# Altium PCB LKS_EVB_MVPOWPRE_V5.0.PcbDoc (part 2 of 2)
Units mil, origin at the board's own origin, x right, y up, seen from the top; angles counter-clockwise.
Board outline 11300 x 7874.02 mil, 2 copper layers (Top Layer, Bottom Layer); 150 components, 96 nets, 404 pads, 334 vias.
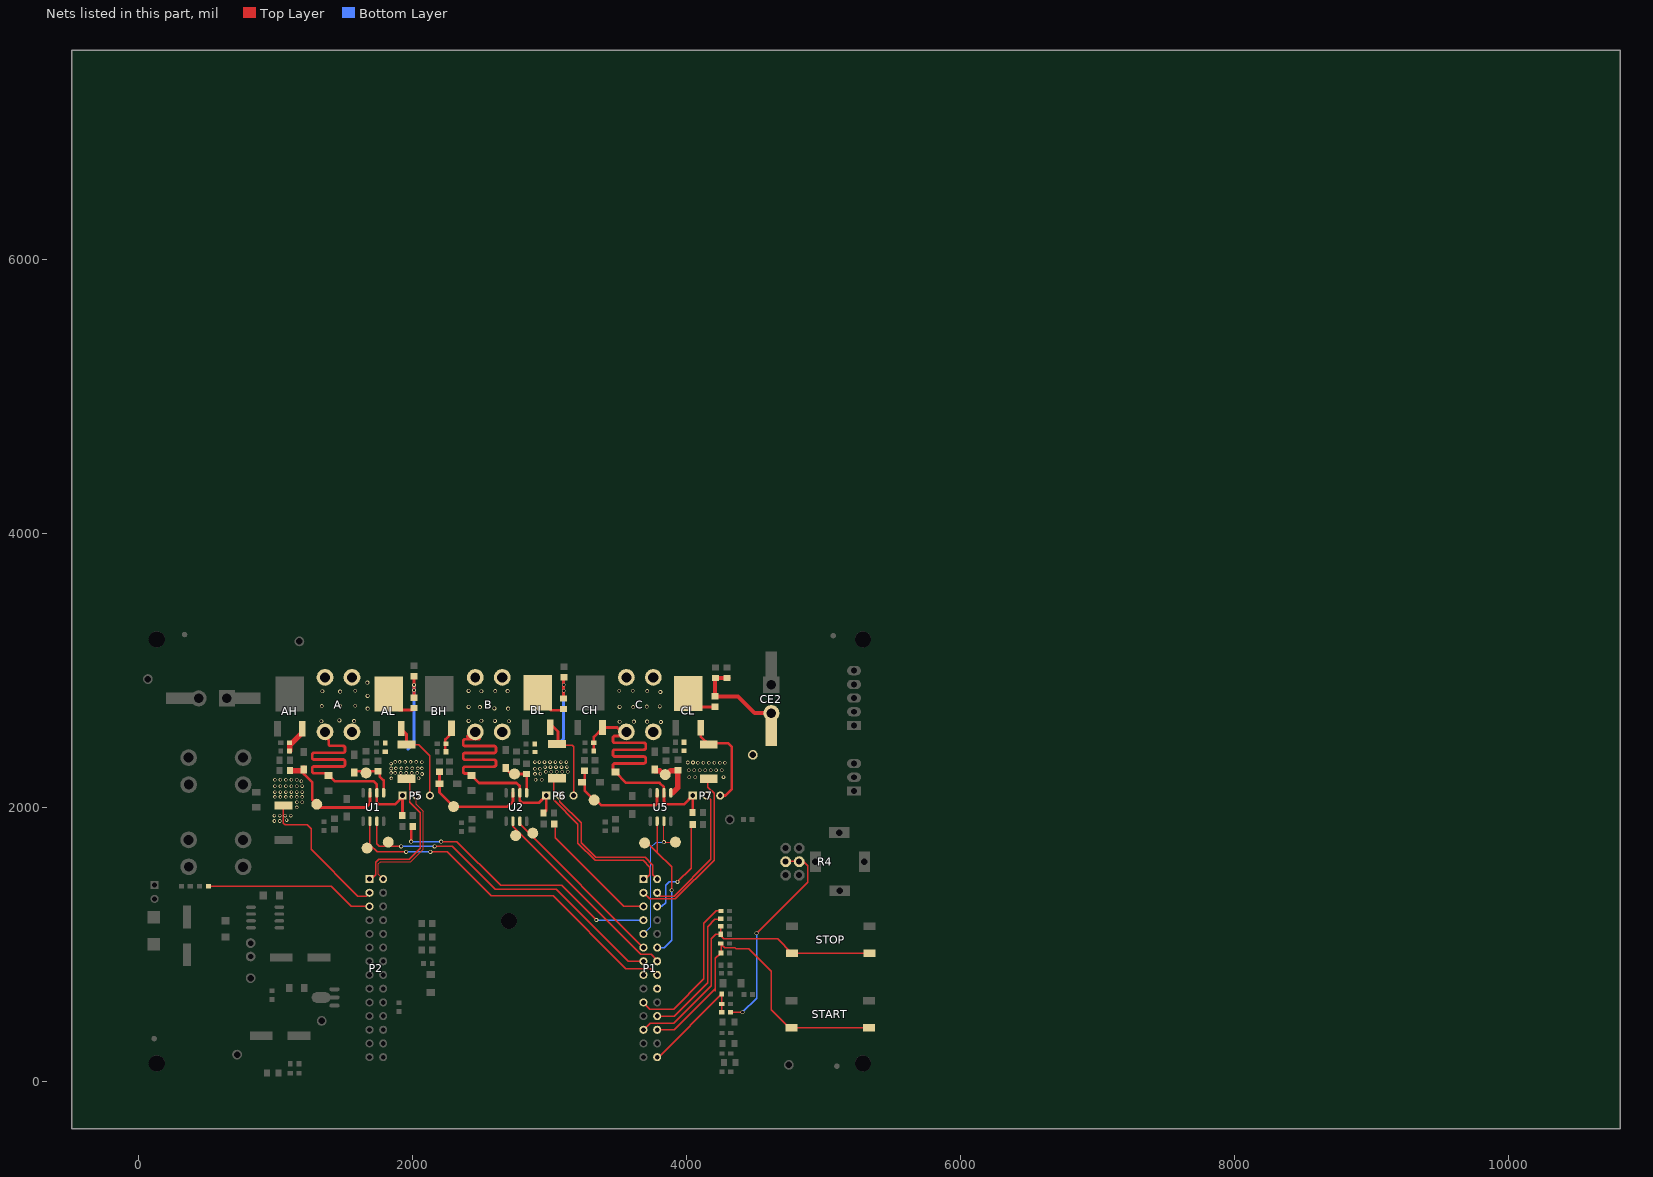
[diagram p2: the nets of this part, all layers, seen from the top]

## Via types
v1: diameter 26, hole 16, Top Layer to Bottom Layer, 130 vias
v2: diameter 28, hole 18, Top Layer to Bottom Layer, 77 vias
v3: diameter 26, hole 18, Top Layer to Bottom Layer, 55 vias
v4: diameter 28, hole 20, Top Layer to Bottom Layer, 54 vias
v5: diameter 23.62, hole 15.75, Top Layer to Bottom Layer, 14 vias
v6: diameter 27.99, hole 20, Top Layer to Bottom Layer, 4 vias

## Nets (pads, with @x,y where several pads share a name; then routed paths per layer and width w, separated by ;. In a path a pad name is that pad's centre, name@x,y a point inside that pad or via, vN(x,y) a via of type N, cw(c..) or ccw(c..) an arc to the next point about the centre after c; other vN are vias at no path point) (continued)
PGND: C25.1 C26.1 C27.1 CE2.2 G1.1 P1.1 P1.2 P2.1 P2.2 R15.2 R16.1 R17.2 R28.1 R29.1 R30.1 R49.2 R69.1 | length 6483
  Top Layer w10: R69.1@1054.64,2011.11 1054.64,1884.12 1067.42,1871.33 1228.67,1871.33 1256.18,1843.82 1256.18,1692.96 1598.21,1350.93 1661.68,1350.93 ; P2.1@1692.67,1471.01 1727.92,1506.26 1727.92,1597.92 1751.19,1621.19 1974.19,1621.19 2054.38,1701.38 2054.38,1959.09 1975.85,2037.61 R15.2@1975.85,2199.1 ; R16.1@3026.4,2195.53 3026.4,2052.72 3204.47,1874.66 3204.47,1735.48 3329.09,1610.86 3682.02,1610.86 3730.05,1562.83 3730.05,1508.37 3696.87,1475.19 P1.1@3682.62,1475.19 ; P1.2@3682.62,1375.19 3727.73,1330.08 3915.11,1330.08 4197.64,1612.61 4197.64,2100.51 4150.95,2147.2 4150.83,2147.2 R17.2@4150.83,2198.71
  Top Layer w20: R28.1@2007.36,2802.08 C25.1@2007.36,2941.01 ; R29.1@3099.13,2793.46 C26.1@3099.13,2931.12
  Top Layer w30: C27.1@4203.92,2942.41 4203.92,2808.13 4372.39,2808.13 4494.4,2686.11 CE2.2@4615.74,2686.11 ; C27.1@4204.13,2942.2 R49.2@4303.26,2942.2
  Bottom Layer w20: 1963.13,2423.19 2007.36,2467.42 v2@2007.36,2889.83 ; 3067.37,2467.7 3099.18,2499.51 v3(3099.18,2893.01)
  other v1: 988.91,1899.15 1027.94,1899.15 1077.76,1905.51 988.91,1938.79 1027.94,1938.79 1067.42,1938.79 1108.08,1938.79 1152.21,1998 1152.65,2036.08 1191.44,2036.08 992.21,2075.37 1032.21,2075.37 1072.21,2075.37 1112.21,2075.37 1152.21,2075.37 1192.21,2075.37 992.21,2110 1032.21,2110 1072.21,2110 1112.21,2110 1152.21,2110 1192.21,2110 992.21,2153.24 1032.21,2153.24 1072.21,2153.24 1112.21,2153.24 1152.21,2153.24 1191.44,2153.63 1186,2190 992.21,2200.54 1032.21,2200.54 1072.21,2200.54 1112.21,2200.54 1152.21,2200.54 2895.06,2200.54 2940,2200.54 1842.79,2210 2041.26,2211.01 4016.05,2217.85 4060,2217.85 4266.76,2220 2066.55,2242 2890.81,2242.5 2930,2244.54 1840,2250 1870.86,2250 1910.86,2250 1950.86,2250 1990.86,2250 2030.86,2250 2970,2259.16 3010,2259.16 3050,2259.16 3090,2259.16 3130,2259.16 4012.91,2269.54 4052.91,2269.54 4092.91,2269.54 4132.91,2269.54 4172.91,2269.54 4212.91,2269.54 4254.12,2269.54 2890,2280.93 2926.25,2280.93 1840.91,2282.5 1875.17,2283.1 1915.17,2283.1 1955.17,2283.1 1995.17,2283.1 2035.17,2283.1 2065,2283.1 2964.02,2292.27 3004.02,2292.27 3044.02,2292.27 3084.02,2292.27 3124.02,2292.27 1840,2318 4080,2324.18 4120,2324.18 4160,2324.18 4200,2324.18 4240,2324.18 4277.03,2324.43 4006,2326 4044,2326 2065,2328 2890,2329.16 2923.26,2329.16 2960,2329.16 3000,2329.16 3040,2329.16 3080,2329.16 3120,2329.16 2024.05,2330.26 1870.86,2330.6 1902.23,2330.6 1942.23,2330.6 1982.23,2330.6
  other v2: 2007.36,2853.62 2007.36,2892.65
  other v3: 3099.19,2849.89
PU: P1.4 R55.1 | length 2039.3
  Top Layer w10: v2(2204.99,1749.27) 2321,1749.27 2639.29,1430.98 3085.99,1430.98 3339,1177.97 v2(3339,1176.63)
  Top Layer w20: v2(1986.61,1749.27) R55.1@1986.61,1854.53
  Bottom Layer w10: v2(1986.61,1749.27) v2(2204.99,1749.27) ; v2(3339,1176.63) 3339.72,1175.91 3681.9,1175.91 P1.4@3682.23,1175.58
PV: P1.3 R59.1 | length 928.2
  Top Layer w10: 3037.12,1850.89 3037.12,1775.34 3537.27,1275.19 P1.3@3682.62,1275.19
PW: P1.17 R61.1 | length 758.7
  Top Layer w10: v2(3930.83,1454.77) 4031.4,1555.34 R61.1@4031.4,1874.57
  Bottom Layer w10: P1.17@3782.62,1275.19 3817.4,1275.19 3845.92,1303.71 3845.92,1431.14 3869.56,1454.77 v2(3930.83,1454.77)
RXD0: P1.25 R9.1 | length 1002.1
  Top Layer w10: P1.25@3782.62,475.19 3906.46,475.19 4150,718.73 4150,1127.58 4202.9,1180.48 R9.1@4253.03,1180.48
RXD1: P1.23
SPIN: C19.2 P1.28 R42.2 R43.2 | length 796.1
  Top Layer w10: P1.28@3782.62,175.19 3792.98,175.19 C19.2@4254.37,636.63 ; R42.2@4254.37,503.95 C19.2@4254.37,636.63 ; C19.2@4254.76,636.97 C19.2@4254.37,636.63
START1: C2.2 P1.26 R7.2 START.2 START.4 | length 2400.7
  Top Layer w10: P1.26@3782.62,375.19 3907.1,375.19 4203.83,671.92 ; 4206.88,657.72 4206.88,895.59 4242.39,931.1 C2.2@4254.41,931.1 ; C2.2@4250.17,938.74 R7.2@4250.17,994.53 ; R7.2@4250.68,996.98 4273.94,973.72 4350.97,973.72 4356.31,968.39 4451.82,968.39 4616.45,803.76 4616.45,520.71 START.2@4762.71,374.44 ; START.2@4764.7,389.13 START.4@5329.64,389.13
STOP1: C3.1 P1.12 R13.1 STOP.2 STOP.4 | length 2268
  Top Layer w10: P1.12@3682.62,375.19 3684.11,375.19 3732.88,423.96 3904.57,423.96 4178.27,697.66 4178.27,1040.69 4209.96,1072.38 C3.1@4247,1072.38 ; R13.1@4247.41,1122.52 4247.41,1062.67 C3.1@4246.51,1061.77 ; STOP.2@4765.66,933.83 4660.82,1038.67 4345.16,1038.67 4269.6,1038.67 C3.1@4246.51,1061.77 ; STOP.2@4766.4,933.98 STOP.4@5333.33,933.98 ; C3.1@4246.51,1061.77 4246.51,1062.82 4252.77,1061.77 C3.1@4246.51,1061.77
TXD0: P1.10 R12.2 | length 1120.6
  Top Layer w10: P1.10@3682.62,575.19 3682.62,573.73 3729.86,526.49 3902.86,526.49 4123.15,746.78 4123.15,1153.46 4212.07,1242.38 R12.2@4247.38,1242.38
TXD1: P1.8
U_N: P1.7 T2.1 U1.3 | length 2466.8
  Top Layer w10: U1.3@1736.11,1897.79 1736.11,1732.69 1755.5,1713.3 v2(1913.52,1713.3) ; v2(2157.85,1713.3) 2286.7,1713.3 2600,1400 3045.72,1400 3570.53,875.19 P1.7@3682.62,875.19
  Bottom Layer w10: v2(1913.52,1713.3) v2(2157.85,1713.3)
U_N-: D8.2 R22.2 T4.1 U1.5 | length 353
  Top Layer w20: D8.2@1571.43,2252.91 1581.52,2263 R22.2@1745.67,2263 1757.04,2251.63 1757.04,2223.35 1786.11,2194.28 U1.5@1786.11,2105.16
U_P: P1.22 T1.1 U1.2 | length 2665.2
  Top Layer w10: U1.2@1686.11,1897.79 1686.11,1726.5 1739.15,1673.47 v2(1949.5,1673.47) ; v2@2123.58,1673.47 2251.53,1673.47 2571.78,1353.22 3022.26,1353.22 3553.51,821.97 3735.84,821.97 P1.22@3782.62,775.19
  Bottom Layer w10: v2(1949.5,1673.47) v2(2126.92,1673.47)
U_P+: D3.2 R11.1 T3.1 U1.7 | length 890.9
  Top Layer w20: D3.2@1203.41,2271.83 1203.41,2241.95 1265.27,2180.09 1265.27,2054.14 T3.1@1297.78,2021.63 1321.4,1998 1655.72,1998 1686.11,2028.4 U1.7@1686.11,2104.79
  Top Layer w40: R11.1@1102,2266 1197.58,2266 1203.41,2271.83 D3.2@1203.41,2282.54
UI: AL.3 C11.2 P5.3 R15.1 R31.1 | length 657.8
  Top Layer w10: R15.1@1953.12,2457.26 2041.26,2457.26 2124.05,2374.46 P5.3@2124.05,2084.61
  Top Layer w20: AL.3@1907.6,2590.59 1907.6,2578.05 1953.12,2532.53 R15.1@1953.12,2446.68
UP: P2.15 P5.2 | length 898.4
  Top Layer w8: P2.15@1782.62,1475.19 1748.06,1509.75 1748.06,1586.91 1763.28,1602.13 1982.13,1602.13 2074.06,1694.06 2074.06,1970.06 2024.05,2020.07 P5.2@2024.05,2075.37
UX: A.1 AH.3 AL.2 C7.2 C28.2 P5.1 R1.2 R21.1 R28.2 U1.6 | length 2430.4
  Top Layer w20: R21.1@1098.67,2469.24 R21.1@1099.35,2469.91 ; A.1@1364.68,2508.84 1384.47,2489.06 1384.47,2462.5 ccw(c1399.47,2462.5) 1399.47,2447.5 1489.47,2447.5 cw(c1489.47,2432.5) 1504.47,2432.5 1504.47,2412.5 cw(c1489.47,2412.5) 1489.47,2397.5 1279.47,2397.5 ccw(c1279.47,2382.5) 1264.47,2382.5 1264.47,2362.5 ccw(c1279.47,2362.5) 1279.47,2347.5 1489.47,2347.5 cw(c1489.47,2332.5) 1504.47,2332.5 1504.47,2312.5 cw(c1489.47,2312.5) 1489.47,2297.5 1279.47,2297.5 ccw(c1279.47,2282.5) 1264.47,2282.5 1264.47,2262.5 ccw(c1279.47,2262.5) 1279.47,2247.5 1369.47,2247.5 cw(c1369.47,2232.5) 1384.46,2232.69 cw(c1369.47,2232.5) C28.2@1384.47,2232.5 ; C28.2@1382.65,2230.41 1387.65,2230.41 1428.06,2190 1710.52,2190 1736.11,2164.41 U1.6@1736.11,2104.79 1736.11,2035.15 1750.16,2021.1 1869.78,2021.1 1924.05,2075.37 R1.2@1924.05,1940.22 ; AL.2@1850.99,2777.28 1850.99,2759.79 1900.57,2710.21 R28.2@1998.27,2710.21 ; P5.1@1924.05,2071.07 P5.1@1925.47,2072.49
  Top Layer w40: C7.2@1099.35,2411.48 1099.35,2450.31 1191.38,2542.35 AH.3@1191.38,2573.85
  other v2: 1331.6,2627.07 1570.26,2628.61 1462.48,2633.23 1668.8,2720 1333.91,2737.93 1467.87,2737.93 1578.73,2740 1668.8,2812.61 1467.87,2843.4 1338.53,2845.71 1578.73,2849.56 1667.66,2908.9
V_N: P1.6 T6.1 U2.3 | length 1314.9
  Top Layer w10: U2.3@2779.94,1901 2779.94,1877.87 P1.6@3682.62,975.19 ; P1.6@3690.59,972.72 P1.6@3690.59,987.92
V_N-: D10.2 R24.2 T8.1 U2.5 | length 307.6
  Top Layer w20: D10.2@2677.05,2286.97 2677.05,2281.46 2716.51,2242 R24.2@2829.94,2242 U2.5@2829.94,2109.17
V_P: P1.21 T5.1 U2.2 | length 1495.7
  Top Layer w10: U2.2@2729.94,1901 2729.94,1859.76 3663.93,925.77 3738.92,925.77 P1.21@3780.36,884.34
V_P+: D9.2 R23.1 T7.1 U2.7 | length 812
  Top Layer w20: R23.1@2193.35,2257.93 D9.2@2193.35,2169.59 2193.35,2107.33 T7.1@2296.5,2004.18 2296.9,2003.78 2691.84,2003.78 2729.94,2041.88 U2.7@2729.94,2104.79 U2.7@2729.94,2108
VI: BL.3 C20.2 P6.3 R16.2 R45.1 | length 647.2
  Top Layer w10: R16.2@3069.22,2452.72 3162.43,2452.72 3172.79,2442.37 P6.3@3172.79,2084.61
  Top Layer w20: BL.3@2998.69,2592.01 3018.44,2592.01 3058.8,2551.65 R16.2@3058.8,2446.89
VOL_ADC: P2.3 R75.2 | length 1241.3
  Top Layer w10: R75.2@502.86,1423.85 1402.56,1423.85 1551.22,1275.19 P2.3@1682.62,1275.19
VP: P1.15 P6.2 | length 1113.8
  Top Layer w10: P6.2@3072.79,2084.61 3072.79,2040.53 3228.42,1884.9 3228.42,1741.58 3335.36,1634.64 3694.4,1634.64 3751.62,1577.42 3751.62,1506.19 P1.15@3782.62,1475.19
VX: B.1 BH.3 BL.2 C16.2 C29.2 P6.1 R2.2 R29.2 R39.1 U2.6 | length 2533.7
  Top Layer w20: C16.2@2236.13,2404.29 2236.13,2494.84 BH.3@2282.81,2541.52 ; 2397.09,2515.18 2416.34,2495.93 ; C29.2@2426.51,2232.17 2482.68,2176 2756.51,2176 2779.94,2152.57 2779.94,2048.48 2795.9,2032.51 2920.7,2032.51 P6.1@2972.79,2084.61 2972.79,1977.87 R2.2@2952.16,1957.24 ; C29.2@2432.64,2230.24 2416.95,2245.93 2381.33,2245.93 cw(c2381.33,2260.93) 2366.33,2260.93 2366.33,2280.93 cw(c2381.33,2280.93) 2381.33,2295.93 2591.33,2295.93 ccw(c2591.33,2310.93) 2606.33,2310.93 2606.33,2330.93 ccw(c2591.33,2330.93) 2591.33,2345.93 2381.33,2345.93 cw(c2381.33,2360.93) 2366.33,2360.93 2366.33,2380.93 cw(c2381.33,2380.93) 2381.33,2395.93 2591.33,2395.93 ccw(c2591.33,2410.93) 2606.33,2410.93 2606.33,2430.93 ccw(c2591.33,2430.93) 2591.33,2445.93 2381.33,2445.93 cw(c2381.33,2460.93) 2366.33,2460.93 2366.33,2480.93 cw(c2381.33,2480.93) 2381.33,2495.93 2416.34,2495.93 ; B.1@2486.33,2502.19 cw(c2480.08,2502.19) 2480.08,2495.93 2416.34,2495.93 ; BL.2@2958.42,2755.46 3006.07,2707.81 R29.2@3099.15,2707.81
  other v2: 2700.76,2626.75 2406.43,2630 2597.97,2629.4 2498.97,2631.15 2694.72,2719.23 2594.23,2720.88 2488.8,2730.76 2406.43,2732.41 2499.51,2846.07 2600,2846.9 2690.6,2846.9 2406.43,2848.55
W_N: P1.5 T10.1 U5.3 | length 998
  Top Layer w7.87: U5.3@3832.06,1894.22 v2(3832.06,1745.36) T10.1@3915.7,1745.36
  Bottom Layer w7.87: P1.5@3682.62,1075.19 3735.91,1128.48 3735.91,1706.19 3775.07,1745.36 v2(3832.06,1745.36)
W_N-: D12.2 R26.2 T12.1 U5.5 | length 382.7
  Top Layer w20: U5.5@3882.06,2101.22 U5.5@3882.06,2104.79
  Top Layer w40: D12.2@3764.75,2275.04 3764.75,2269.53 3768.77,2265.51 3802.34,2265.51 3830.24,2237.61 T12.1@3841.07,2237.61 3851.89,2237.61 3881.29,2267 3930,2267 R26.2@3933,2270 3933,2142.37 3897,2106.37 ; T12.1@3846.44,2224 T12.1@3846.6,2224
W_P: P1.20 T9.1 U5.2 | length 1179.6
  Top Layer w10: T9.1@3691.07,1738.42 3713.42,1738.42 3798.2,1653.63 ; U5.2@3782.06,1894.22 3782.06,1669.09 3887.7,1563.44 v2(3887.7,1393.54)
  Bottom Layer w10: P1.20@3782.62,975.19 3835.62,975.19 3887.7,1027.28 v2(3887.7,1393.54)
W_P+: D11.2 R25.1 T11.1 U5.7 | length 775.6
  Top Layer w20: R25.1@3253,2266 3253,2121.87 T11.1@3322.69,2052.18 ; T11.1@3343.01,2044.95 3374.72,2013.23 3769.68,2013.23 3782.06,2025.61 U5.7@3782.06,2101.22
WI: C34.2 CL.3 P7.3 R17.1 R63.1 | length 720.1
  Top Layer w20: CL.3@4099.96,2578.67 4099.96,2517.38 R17.1@4159.26,2458.08 ; R17.1@4175.37,2465.89 4302.15,2465.89 4326.22,2441.82 4326.22,2130.48 4280.34,2084.61 P7.3@4242.39,2084.61
WP: P1.16 P7.2 | length 994.5
  Top Layer w10: P1.16@3782.62,1375.19 3806.76,1351.05 3907.8,1351.05 4175.37,1618.62 4175.37,2053.74 4144.5,2084.61 P7.2@4142.39,2084.61
WX: C24.2 C30.2 C.1 CH.3 CL.2 P7.1 R3.2 R30.2 R50.1 U5.6 | length 2780.2
  Top Layer w20: C24.2@3319.99,2409.07 3319.99,2512.3 CH.3@3384.66,2576.98 ; CH.3@3384.25,2581.28 3490.4,2581.28 C.1@3548.18,2523.5 ; C30.2@3474.41,2269.54 cw(c3474.41,2284.54) 3459.41,2284.54 3459.41,2304.54 cw(c3474.41,2304.54) 3474.41,2319.54 3684.41,2319.54 ccw(c3684.41,2334.54) 3699.41,2334.54 3699.41,2354.54 ccw(c3684.41,2354.54) 3684.41,2369.54 3474.41,2369.54 cw(c3474.41,2384.54) 3459.41,2384.54 3459.41,2404.54 cw(c3474.41,2404.54) 3474.41,2419.54 3684.41,2419.54 ccw(c3684.41,2434.54) 3699.41,2434.54 3699.41,2454.54 ccw(c3684.41,2454.54) 3684.41,2469.54 3474.41,2469.54 cw(c3474.41,2484.54) 3459.41,2484.54 3459.41,2504.54 cw(c3474.41,2504.54) 3474.41,2519.54 3570.95,2519.54 ccw(c3570.95,2528.01) C.1@3579.41,2528.01 ; C30.2@3477.64,2256.04 3555.68,2178 3799.22,2178 3831.29,2145.92 3831.29,2105.55 U5.6@3832.06,2104.79 3832.06,2041.06 3852.31,2020.81 3978.59,2020.81 P7.1@4042.39,2084.61 ; CL.2@4009.41,2830.64 4108.19,2731.86 R30.2@4205.02,2731.86 ; R3.2@4042.39,1966.26 P7.1@4042.39,2092.38
  other v2: 3810,2621.72 3507.98,2623.63 3612.44,2624.9 3708.42,2624.9 3608.08,2730.44 3507.98,2732.17 3706.46,2733.89 3801.38,2735.62 3806.55,2840.9 3709.91,2847.8 3506.26,2849.53 3604.63,2849.53
ZB: R4.3 R4.5 R42.1 | length 1528.1
  Top Layer w10: R42.1@4314.88,503.39 v4(4405,503.39) ; v4@4508.26,1080.84 4880,1452.58 4880,1572.7 4847.49,1605.2 R4.5@4817.62,1605.2 ; R4.3@4719.87,1604.09 R4.5@4816.46,1604.09
  Bottom Layer w10: v4(4405,503.39) 4508.01,606.39 v4@4508.01,1080.46
  other v4: 4508.07,1080.22
pads on no net: R4.0 U4.3 U4.6

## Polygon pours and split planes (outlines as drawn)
GND on Top Layer "Bottom Layer-No Net" (solid, remove dead copper, pour order 59): 232,989.63 661.77,989.63 661.77,613.23 661.77,565.92 710.33,500 728.74,475 882.77,475 882.77,23.48 881.64,25.01 306.12,25.01 232,25.01
PGND on Top Layer "PGND_L01_P084" (solid, pour order 84): 1800.67,2350.77 1800.67,2186.33 1828.68,2158.32 2088.73,2158.32 2100,2169.59 2100,2341.12 2091,2350.12
PGND on Top Layer "PGND_L01_P083" (solid, pour order 83): 2873,2350 2873,2165 2889.29,2148.71 3135.51,2148.71 3151,2164.2 3151,2348 3152,2349
PGND on Top Layer "PGND_L01_P082" (solid, pour order 82): 3979,2347 3979,2153 3997.39,2134.61 4284.6,2134.61 4301,2151 4301,2347
PGND on Top Layer "Bottom Layer-No Net" (solid, remove dead copper, pour order 68): 972.01,2219.44 972.01,1899.15 1221.02,1899.15 1221.02,2197.68 1221.02,2220.5
GND on Top Layer "Top Layer-No Net 1" (solid, remove dead copper, pour order 79): 1225,1097 1225,798 1405,798 1405,897.16 1405,1097
GND on Top Layer "Bottom Layer-No Net" (solid, remove dead copper, pour order 78): 620,650 663.17,606.83 706.07,606.83 1126.81,606.83 1145.52,588.12 1151.55,582.09 1151.55,388.12 1126.63,388.12 1038.68,300.17 863.74,125.24 720,125.24
+5V on Top Layer "Bottom Layer-No Net" (solid, remove dead copper, pour order 62): 1084.55,495.6 1348.8,495.6 1382.65,495.6 1373.61,484.59 1373.61,184.4 1084.55,184.4
+15V on Top Layer "Bottom Layer-No Net" (solid, remove dead copper, pour order 53): 675,948.95 675,631.45 981.93,631.45 1010.28,659.8 1054.68,704.2 1054.68,948.95
GND on Top Layer "Bottom Layer-No Net" (solid, remove dead copper, pour order 76): 836.51,1813.88 1108.08,1813.88 1125.59,1796.37 1128.6,1793.37 1128.6,1642.32 875.52,1642.32 832,1685.83
WI on Top Layer "Top Layer-No Net" (solid, remove dead copper, pour order 46): 3969.62,2639.07 4243.31,2639.07 4266.47,2639.07 4274.19,2631.35 4281.91,2623.63 4281.91,2504.41 4281.91,2431.51 4239.4,2389 3968.57,2389
VI on Top Layer "Top Layer-No Net" (solid, remove dead copper, pour order 51): 2920.78,2638.24 2924.02,2641.48 3100.86,2641.48 3126.25,2641.48 3130.93,2636.79 3140.7,2627.03 3140.7,2469.61 3140.7,2383.67 3136.03,2379 2880.76,2379 2880.76,2638.24
UI on Top Layer "Top Layer-No Net" (solid, remove dead copper, pour order 54): 1827.43,2629.4 1793.17,2595.14 1793.17,2397.5 1800.67,2390 2037.8,2390 2040.98,2393.17 2040.98,2516.3 2040.98,2623.29 2033.12,2631.15
WX on Top Layer "Bottom Layer-No Net" (solid, remove dead copper, pour order 69): 3491.39,3026.45 3459.81,2994.88 3459.81,2969.05 3459.81,2687.07 3424.66,2651.91 3392.37,2619.63 3392.37,2588.06 3392.37,2544.29 3398.11,2538.55 3438.29,2498.37 3719.55,2498.37 3809.95,2498.37 3828.61,2517.03 3834.35,2522.77 3834.35,2605.28 3834.35,2647.61 3847.97,2661.23 3858.02,2671.28 3934.79,2671.28 3983.58,2671.28 4013,2700.7 4018.74,2706.44 4018.74,2908.78 4018.74,2968.33 4010.85,2976.22 3993.63,2993.44 3820,2993.44 3787.71,2993.44 3753.99,3027.16
VX on Top Layer "Bottom Layer-No Net" (solid, remove dead copper, pour order 70): 2388.57,3013.8 2357,2982.22 2357,2956.39 2357,2674.42 2321.84,2639.26 2289.55,2606.97 2289.55,2575.41 2289.55,2531.64 2295.29,2525.9 2335.47,2485.72 2616.73,2485.72 2707.14,2485.72 2725.79,2504.37 2731.53,2510.11 2731.53,2592.62 2731.53,2634.96 2745.15,2648.58 2755.2,2658.63 2831.97,2658.63 2880.76,2658.63 2910.19,2688.05 2915.93,2693.79 2915.93,2896.13 2915.93,2955.68 2908.03,2963.57 2890.81,2980.79 2717.18,2980.79 2684.89,2980.79 2651.17,3014.51
UX on Top Layer "Bottom Layer-No Net" (solid, remove dead copper, pour order 71): 1300.98,3012.37 1269.41,2980.8 1269.41,2954.97 1269.41,2673 1234.25,2637.84 1201.96,2605.55 1201.96,2573.98 1201.96,2530.22 1207.7,2524.48 1247.88,2484.3 1529.14,2484.3 1619.55,2484.3 1638.2,2502.95 1643.94,2508.69 1643.94,2591.2 1643.94,2633.54 1657.56,2647.16 1667.61,2657.2 1744.38,2657.2 1793.17,2657.2 1822.6,2686.63 1828.34,2692.37 1828.34,2894.7 1828.34,2954.26 1820.44,2962.15 1803.22,2979.37 1629.59,2979.37 1597.3,2979.37 1563.58,3013.09
GND on Top Layer "Bottom Layer-No Net" (solid, remove dead copper, pour order 72): 1056.92,1729.18 1061.21,1729.18 1114.4,1652.94 1122.98,1640.65 1122.98,1538.59 1122.98,1529.98 1108.39,1509.08 1107.54,1510.31 740.39,1510.31 50.69,1510.31 -41.95,1643.11 22.4,1735.34 22.4,1908.71 22.4,1983.71 31.83,1997.24 39.54,2008.29 791,2008.29 823.61,2008.29 840.76,1983.71 865.63,1948.07 865.63,1759.92 865.63,1731.64 864.77,1730.41
GND on Top Layer "Bottom Layer-No Net" (solid, remove dead copper, pour order 66): 275.62,1983.9 225.61,2033.91 225.61,2175.26 225.61,2640.63 298.45,2713.47 450.68,2865.71 450.68,2959.22 450.68,3001.62 415.89,3036.41 401.75,3050.55 221.26,3050.55 126.66,3050.55 51.64,2975.52 19.02,2942.9 19.02,1982.81
+48V on Top Layer "Bottom Layer-No Net" (solid, remove dead copper, pour order 63): 653.24,3316.24 645.5,3316.24 614.5,3285.24 612.95,3283.69 612.95,2948.92 612.95,2807.88 535.45,2730.38 295.97,2490.89 295.97,2411.36 295.97,2157.73 313.82,2139.88 318.47,2135.23 653.24,2135.23 851.63,2135.23 871.78,2155.38 896.58,2180.18 896.58,2218.92 896.58,2673.04 941.52,2717.98 944.63,2714.88 1042.26,2714.88 1161.6,2714.88 1197.26,2750.54 1205,2758.28 1205,2959.76 1205,3035.71 1253.05,3083.76 1511.88,3083.76 1958.24,3083.76 1996.99,3045.01 2102.38,2939.62 2102.38,2869.87 2271.32,2869.87 2274.42,2872.97 2288.37,2886.92 2288.37,2978.36 2288.37,3004.71 2317.82,3034.16 2367.41,3083.76 2517.75,3083.76 3072.61,3083.76 3116,3040.36 3195.05,2961.31 3195.05,2891.57 3202.8,2891.57 3226.04,2868.32 3229.14,2865.22 3363.98,2865.22 3381.03,2865.22 3388.78,2872.97 3388.78,2952.01 3388.78,3031.06 3429.08,3071.36 3433.73,3076.01 4080.03,3076.01 4140.47,3076.01 4185.42,3031.06 4186.97,3032.61 4360.56,3032.61 4388.45,3032.61 4413.25,3007.81 4464.4,2956.66 4464.4,2928.77 4464.4,2893.12 4479.9,2877.62 4484.54,2872.98 4783.68,2872.98 4805.38,2872.98 4831.72,2899.32 4831.71,2899.33 4831.71,3268.18 4831.71,3300.75 4751.13,3381.33
PGND on Top Layer "Bottom Layer-No Net" (solid, remove dead copper, pour order 55): 4373.45,2728.34 4719.43,2728.34 4747.94,2699.83 4758.73,2689.04 4758.73,2397 4758.73,2394.69 4589.21,2225.16 4407.35,2225.16 4370.37,2225.16
GND on Top Layer "Bottom Layer-No Net" (solid, remove dead copper, pour order 48): 996,1130.83 1000.17,1135 1217.31,1135 1367,1135 1405,1097 1394,1086 1394,1032 1008,1032 996,1044
NetCE3_1 on Top Layer "Bottom Layer-No Net" (solid, remove dead copper, pour order 47): 250,1075.19 474.16,1075.19 474.58,1075.61 474.58,1193.58 533.31,1252.31 533.62,1252 747,1252 747,1365 745.61,1363.61 274.49,1363.61 250,1339.13
NetC1_2 on Top Layer "Bottom Layer-No Net" (solid, remove dead copper, pour order 50): 854,1131.07 853.93,1131 795,1131 765.03,1131 750.03,1116 727.03,1093 684,1093 597.92,1093 580,1075.08 580,992.01 580,990.52 600.15,970.37 600.52,970 891,970 892.79,970 910,987.21 910,1092.29
NetR34_1 on Top Layer "Bottom Layer-No Net" (solid, remove dead copper, pour order 52): 570,1228 548.62,1228 533.62,1213 528,1207.38 528,1159 528,1132.62 533.62,1127 546.62,1114 662,1114 701,1114 746,1159 746,1183 746,1210 728,1228
GND on Bottom Layer "Bottom Layer-No Net" (solid, remove dead copper, pour order 64): 1915.23,895.54 1795.55,895.54 1758.68,895.54 1590,726.86 1528.01,664.87 1528.01,239.87 1528.01,-10 1548.01,-30 5160,-30 5160,279.7 5460,279.7 5460,1775.36 5260,1975.36 5241.29,1994.07 4189.35,1994.07 4154.07,1994.07 4110,1950 3999.04,1839.04 3999.04,962.69 3931.89,895.54
PGND on Bottom Layer "PGND_L02_P085" (solid, pour order 85): 1349.35,2180.09 1347.98,2178.72 1347.98,2105 1127.09,1884.12 972.3,1884.12 972.3,2057.05 969.94,2059.41 1030.53,2120 1075,2120
GND on Bottom Layer "Bottom Layer-No Net" (solid, remove dead copper, pour order 65): 277.24,1643.78 227.22,1709.79 227.22,1896.32 227.22,2510.43 300.06,2606.55 452.29,2807.44 452.29,2930.83 452.29,2986.79 417.5,3032.71 403.37,3051.36 222.87,3051.36 128.28,3051.36 53.25,2952.36 20.63,2909.31 20.63,1642.35
GND on Bottom Layer "Top Layer-No Net 1" (solid, remove dead copper, pour order 81): 264,835 550,835 550,672.83 584,638.83 706,638.83 955.51,638.83 997.91,681.23 997.91,814 997.91,835 1430,835 1528.01,736.99 1528.01,275.19 1527.82,275 1527.63,275.19 264,275.19 264,275
GND on Bottom Layer "Top Layer-No Net 1" (solid, remove dead copper, pour order 80): 1005,1095.03 1164.97,1095.03 1165,1095 1354.98,1095 1365,1095 1487,973 1634.37,825.63 1634.37,723 1634.37,661.37 1576,603 1574.17,601.17 1100.87,601.17 1032.83,601.17 1005,629
GND on Bottom Layer "Top Layer-No Net 1" (solid, remove dead copper, pour order 74): 3961.39,1778.69 3197.31,1778.69 3195.67,1780.7 3193.71,1778.29 2731.04,1778.29 2223.29,1778.29 2221.75,1776.4 1868.65,1776.4 1681.46,1776.4 1585.07,1894.73 1584.01,1896.03 1343.84,1896.03 1343.84,1871.33 1310.41,1830.3 1309.71,1829.43 1094.38,1829.43 1094.38,1854.63 1197.81,1981.6 1333.94,2148.71 1362.02,2148.71 3960.59,2148.71 3961.93,2150.36
PGND on Bottom Layer "Top Layer-No Net" (solid, remove dead copper, pour order 73): 1007.88,1976.98 969.94,2014.92 969.94,2103.9 969.94,2423.65 990.45,2444.16 996.32,2450.02 1144.35,2450.02 1162.88,2450.02 1199.99,2412.92 1207.86,2405.05 1590.03,2405.05 1633.65,2405.05 1727.92,2499.32 1732.21,2503.6 2231.15,2503.6 2231.36,2503.6 2322.51,2412.46 2322.6,2412.37 2586.66,2412.37 2739.44,2412.37 2816.92,2489.85 2835.74,2508.67 3283.93,2508.67 3314.35,2508.67 3383.86,2439.16 3396.88,2426.13 3841.46,2426.13 3846.53,2426.13 3921.11,2500.71 3924.73,2504.33 4236.8,2504.33 4249.11,2504.33 4313.55,2568.77 4358.44,2613.66 4358.44,2691.86 4358.44,2717.93 4368.58,2728.06 4374.37,2733.85 4506.87,2733.85 4754.35,2733.85 4772.45,2715.75 4775.5,2712.7 4775.5,2313.9 4775.5,2208.19 4761.02,2193.7 4746.39,2179.08 4207.6,2179.08 1275.04,2179.08 1233.89,2137.93 1159.54,2063.58 1159.54,1992.53 1159.54,1990.77 1145.75,1976.98
+48V on Bottom Layer "Bottom Layer-No Net" (solid, remove dead copper, pour order 61): 650.66,3314.49 642.92,3314.49 611.92,3283.5 610.37,3281.95 610.37,2947.17 610.37,2806.13 532.87,2728.64 293.39,2489.15 293.39,2409.62 293.39,2155.99 311.24,2138.14 315.89,2133.49 650.66,2133.49 849.05,2133.49 869.2,2153.63 894,2178.43 894,2217.18 894,2671.29 938.94,2716.24 942.05,2713.13 1039.68,2713.13 1159.02,2713.13 1194.68,2748.8 1202.42,2756.54 1202.42,2958.02 1202.42,3033.97 1250.47,3082.01 1509.3,3082.01 1955.66,3082.01 1994.41,3043.26 2099.8,2937.87 2099.8,2868.13 2268.74,2868.13 2271.84,2871.23 2285.79,2885.18 2285.79,2976.62 2285.79,3002.97 2315.24,3032.42 2364.83,3082.01 2515.17,3082.01 3070.03,3082.01 3113.42,3038.62 3192.47,2959.57 3192.47,2889.83 3200.22,2889.83 3223.46,2866.58 3226.56,2863.48 3361.4,2863.48 3378.45,2863.48 3386.2,2871.23 3386.2,2950.27 3386.2,3029.32 3426.5,3069.61 3431.15,3074.26 4077.45,3074.26 4137.89,3074.26 4182.84,3029.32 4184.39,3030.87 4357.98,3030.87 4385.87,3030.87 4410.67,3006.07 4461.82,2954.92 4461.82,2927.02 4461.82,2891.38 4477.32,2875.88 4481.96,2871.24 4781.1,2871.24 4802.8,2871.24 4829.14,2897.58 4829.13,2897.58 4829.13,3266.44 4829.13,3299 4748.55,3379.59
GND on Bottom Layer "Bottom Layer-No Net" (solid, remove dead copper, pour order 67): 23.25,2043.25 23.25,1723.7 51.3,1690.85 354.75,1335.47 1216.66,1335.47 1220.49,1335.47 1234.51,1351.9 1233.24,1353.39 1233.24,1502.71 1233.24,1719.22 1256.19,1746.1 1168.21,1849.13 950.19,1849.13 922.14,1849.13 836.71,1949.18 786.98,2007.41 750.01,2007.41
GND on Bottom Layer "Top Layer-No Net" (solid, remove dead copper, pour order 75): 1220.49,1537.69 1312.19,1537.69 1329.57,1555.07 1336.52,1562.02 1336.52,1614.13 1336.52,1861.79 1389.25,1914.52 1397.32,1922.6 1397.32,1971.43 1198.12,1971.43 1168,1941.32 1132.2,1905.51 1132.2,1742.69
UX on Bottom Layer "Bottom Layer-No Net" (solid, remove dead copper, pour order 58): 1300.61,3010.77 1269.04,2979.2 1269.04,2977.76 1269.04,2671.39 1201.59,2603.95 1201.59,2528.61 1247.51,2482.69 1619.18,2482.69 1637.83,2501.35 1643.57,2507.09 1643.57,2631.93 1667.24,2655.6 1792.8,2655.6 1965.2,2655.6 1970,2660.4 1970,2670.4 1970,3000.4 1960,3010.4
VX on Bottom Layer "Bottom Layer-No Net" (solid, remove dead copper, pour order 57): 2390.21,3011.38 2358.64,2979.81 2358.64,2978.37 2358.64,2672 2291.2,2604.56 2291.2,2529.22 2337.12,2483.3 2708.78,2483.3 2727.44,2501.96 2733.18,2507.7 2733.18,2632.54 2756.84,2656.21 2882.41,2656.21 3054.8,2656.21 3059.61,2661.01 3059.61,2671.01 3059.61,3001.01 3049.61,3011.01
WX on Bottom Layer "Bottom Layer-No Net" (solid, remove dead copper, pour order 56): 3488.32,3023.43 3456.75,2991.86 3456.75,2990.43 3456.75,2684.05 3389.31,2616.61 3389.31,2541.27 3435.23,2495.35 3806.89,2495.35 3825.54,2514.01 3831.28,2519.75 3831.28,2644.59 3854.95,2668.26 3980.51,2668.26 4152.91,2668.26 4157.71,2673.06 4157.71,2683.06 4157.71,3013.06 4147.71,3023.06
PGND on Bottom Layer "Bottom Layer-No Net" (solid, remove dead copper, pour order 77): 1145.75,1976.98 1382.65,2213.87 1382.65,2247.5 1215.58,2247.5 1133.84,2165.76
+48V on Bottom Solder "Bottom Layer-No Net" (solid): 4541.89,2975.25 4556.88,2960.26 4556.88,2890.14 4796.03,2890.14 4802.03,2896.13 4822.41,2916.51 4822.41,2948.28 4822.41,3035.19 4781.05,3076.55
WX on Bottom Solder "Top Layer-No Net" (solid): 3493.83,3004.22 3481.35,2991.74 3481.35,2964.29 3481.35,2678.56 3433.93,2631.14 3427.69,2624.9 3427.69,2550.04 3427.69,2532.57 3447.66,2512.61 3448.91,2511.36 3743.38,2511.36 3777.07,2511.36 3792.04,2526.33 3800.77,2535.07 3800.77,2634.89 3800.77,2663.59 3823.23,2686.04 3859.42,2722.23 4067.79,2722.23 4085.26,2722.23 4097.74,2734.71 4097.74,2858.23 4097.74,2924.36 4081.52,2940.59 4069.04,2953.06 3953,2953.06 3785.8,2953.06 3733.39,3005.47
VX on Bottom Solder "Top Layer-No Net" (solid): 2393.81,2999.83 2381.33,2987.35 2381.33,2959.9 2381.33,2674.16 2333.92,2626.75 2327.68,2620.51 2327.68,2545.64 2327.68,2528.18 2347.64,2508.21 2348.89,2506.96 2643.36,2506.96 2677.05,2506.96 2692.02,2521.94 2700.76,2530.67 2700.76,2630.49 2700.76,2659.19 2723.22,2681.65 2759.4,2717.83 2967.78,2717.83 2985.24,2717.83 2997.72,2730.31 2997.72,2853.84 2997.72,2919.97 2981.5,2936.19 2969.02,2948.67 2852.98,2948.67 2685.78,2948.67 2633.38,3001.07
UX on Bottom Solder "Top Layer-No Net" (solid): 1316.08,2991.56 1303.6,2979.08 1303.6,2951.63 1303.6,2665.9 1256.18,2618.48 1249.94,2612.24 1249.94,2537.38 1249.94,2519.91 1269.91,2499.94 1271.16,2498.7 1565.63,2498.7 1599.32,2498.7 1614.29,2513.67 1623.02,2522.4 1623.02,2622.22 1623.02,2650.92 1645.48,2673.38 1681.67,2709.57 1890.04,2709.57 1907.51,2709.57 1919.99,2722.05 1919.99,2845.57 1919.99,2911.7 1903.77,2927.93 1891.29,2940.4 1775.25,2940.4 1608.05,2940.4 1555.64,2992.81
+48V on Bottom Solder "Top Layer-No Net" (solid): 688.48,3279.3 688.48,2905.73 688.48,2867.97 446.06,2625.55 404.33,2583.82 404.33,2373.19 404.33,2172.49 416.25,2160.57 726.24,2160.57 799.76,2160.57 823.61,2184.42 837.52,2198.33 837.52,2460.62 837.52,2643.43 913.02,2718.94 940.84,2746.76 1077.95,2746.76 1107.76,2746.76 1151.47,2790.48 1171.34,2810.35 1171.34,2985.21 1171.34,3028.93 1221.02,3078.6 1244.87,3102.45 2063.54,3102.45 4668.6,3102.45 4684.5,3118.34 4708.35,3142.19 4708.35,3267.38 4708.35,3291.22 4688.48,3311.09 4686.49,3313.08 3323.35,3313.08 702.26,3313.08 688.39,3299.21
+48V on Bottom Solder "Bottom Layer-No Net" (solid): 4371.83,3119.74 4412.02,3119.74 4486.15,3036.58 4541.58,2974.4 4782.01,2974.4 4804.18,2974.4 4827.74,3000.84 4835.36,3009.38 4835.36,3202.13 4835.36,3270.53 4812.49,3296.18 4797.43,3313.08 4652.33,3313.08
PGND on Bottom Solder "Top Layer-No Net" (solid): 1018.67,2406.75 996.43,2384.52 996.43,2291.93 996.43,2048.62 1021.51,2023.55 1034.38,2010.67 1121.13,2010.67 1152.99,2010.67 1174.67,2032.36 1199.86,2057.54 1199.86,2103.9 1199.86,2163.27 1236.35,2199.76 1240.53,2203.94 2292.63,2203.94 4693.43,2203.94 4732.6,2243.11 4735.57,2246.09 4735.57,2545.85 4735.57,2686.43 4727.39,2694.61 4721.44,2700.56 4481.93,2700.56 4435.07,2700.56 4414.25,2679.73 4394.91,2660.39 4394.91,2621.72 4394.91,2598.66 4351.02,2554.77 4287.05,2490.8 4209.7,2490.8 4208.81,2490.8 4124.4,2406.4

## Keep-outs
Keep-Out Layer:
  lines w5: 91.62,0.36 5330.64,0.36 ccw(c5330.64,84.52) 5414.8,84.52 5414.8,3267.95 ccw(c5328.19,3267.95) 5328.19,3354.57 86.84,3354.57 ccw(c86.84,3267.95) 0.23,3267.95 0.23,91.75 ccw(c91.97,91.74) 91.98,0.01
  lines w9.97: 9514.64,-290.47 9514.64,9.42 ; 9514.64,9.53 9514.64,309.42
  lines w10: -484.2,652.26 -439.2,652.26 ; -484.2,1652.26 -439.2,1652.26 ; -484.2,2652.26 -439.2,2652.26 ; -484.2,3652.26 -439.2,3652.26 ; -484.2,4652.26 -439.2,4652.26 ; -484.2,5652.26 -439.2,5652.26 ; -484.2,6652.26 -439.2,6652.26 ; 510.8,-347.74 510.8,-297.74 ; 510.8,7477.26 510.8,7527.26 ; 1510.8,-347.74 1510.8,-297.74 ; 1510.8,7477.26 1510.8,7527.26 ; 2510.8,-347.74 2510.8,-297.74 ; 2510.8,7477.26 2510.8,7527.26 ; 3510.8,-347.74 3510.8,-297.74 ; 3510.8,7477.26 3510.8,7527.26 ; 4510.8,-347.74 4510.8,-297.74 ; 4510.8,7477.26 4510.8,7527.26 ; 5510.8,-347.74 5510.8,-297.74 ; 5510.8,7477.26 5510.8,7527.26 ; 6510.8,-347.74 6510.8,-297.74 ; 6510.8,7477.26 6510.8,7527.26 ; 7510.8,-347.74 7510.8,-297.74 ; 7510.8,7477.26 7510.8,7527.26 ; 8510.8,-347.74 8510.8,-297.74 ; 8510.8,7477.26 8510.8,7527.26 ; 9510.8,-347.74 9510.8,-297.74 ; 9510.8,7477.26 9510.8,7527.26 ; 10510.8,-347.74 10510.8,-297.74 ; 10510.8,7477.26 10510.8,7527.26 ; 10765.8,652.26 10810.8,652.26 ; 10765.8,1652.26 10810.8,1652.26 ; 10765.8,2652.26 10810.8,2652.26 ; 10765.8,3652.26 10810.8,3652.26 ; 10765.8,4652.26 10810.8,4652.26 ; 10765.8,5652.26 10810.8,5652.26 ; 10765.8,6652.26 10810.8,6652.26

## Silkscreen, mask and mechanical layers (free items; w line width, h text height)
Top Overlay:
  drawing of 484 lines, arcs and shapes, not listed
  text "5414.571 (mil)" at 2313.1,3395.34 h60
  text "LKS _EVB_MVPOWPRE_V5.0" at 3326.55,3221.85 h40
  text "VCC" at 990,3190 h40
  text "HALL" at 5082.79,3113.94 h40
  text "V" at 2524.12,3084.71 h120
  text "U" at 1384.73,3076.89 h120
  text "W" at 3589.9,3069.62 h120
  text "5VH" at 4922.21,2969.31 h40
  text "HA" at 4964.94,2871.74 h40
  text "HB" at 4967.36,2773.37 h40
  text "HC" at 4969.06,2669.69 h40
  text "GND" at 4897.04,2574.61 h40
  text "RXD" at 4925.85,2297.07 h40
  text "PGND" at 4410.8,2270.41 h40
  text "TXD" at 4920.09,2194.32 h40
  text "VCC" at 210.02,2127.23 h80 r90
  text "GND" at 4916.24,2097.32 h40
  text "3354.573 (mil)" at -111.7,2065.85 h60 r270.09
  text "GND" at 4265.48,1973.1 h40
  text "跳帽连接右端是三电阻采样" at 2255.28,1671.89 h100
  text "跳帽连接左端是三相MOS内阻采样" at 2253.8,1575.25 h100
  text "GND" at 223.11,1564.45 h80 r90
  text "STOP" at 4816.56,1288.62 h40
  text "START" at 4814.59,740.64 h40
  text "15V" at 892.79,729.66 h40
  text "5V" at 1406.79,425.24 h40
  text "GND" at 663.95,275 h40
  text "GND" at 4826.57,106.22 h40
Bottom Overlay:
  drawing of 452 lines, arcs and shapes, not listed
Top Solder:
  circle w78.74: c5093.34,111.19 r17.13
  circle w78.74: c5066.78,3254.07 r17.13
  circle w78.74: c110.86,311.12 r17.13
  circle w78.74: c331.81,3261.97 r17.13
Mechanical 1:
  lines w5: 0.23,91.74 ccw(c91.97,91.74) 91.98,0.01 5330.64,0.36 ; 5414.8,84.52 5414.8,3267.95
  lines w9.97: 7272.19,14.42 10761.17,14.42 ; 7272.19,314.31 10761.17,314.31 ; 7272.19,614.2 10761.17,614.2 ; 7770.62,-285.47 7770.62,14.42 7770.62,314.31 7770.62,614.2 7770.62,914.09 ; 8468.42,-285.47 8468.42,14.42 8468.42,314.31 8468.42,614.2 8468.42,914.09 ; 9066.53,14.42 9066.53,314.31 9066.53,614.2 9066.53,914.09
  lines w10: -489.2,7526.27 -489.2,-347.74 10810.01,-347.74 ; -489.2,7527.26 10810.01,7527.26 ; 10810.8,-347.74 10810.8,7526.27 ; -439.2,-297.74 -439.2,7477.26 10760.8,7477.26 10760.8,-297.74 -439.2,-297.74
  lines w29.91: 7272.19,-285.47 10761.17,-285.47 10761.17,914.09 7272.19,914.09 7272.19,-285.47
  text "Design" at 7360.8,732.26 h60
  text "LiuHZ" at 7980.8,732.26 h60
  text "File Name" at 8515.8,732.26 h60
  text "LKS_EVB_MVPOWPRE_V5.0" at 9153,731 h60
  text "LKS Mid. Volt. Demo" at 9165.8,487.26 h60
  text "Check" at 7390.8,432.26 h60
  text "Project" at 8595.8,432.26 h60
  text "Power Base Plate" at 9165.8,377.26 h60
  text "Version" at 8590.8,132.26 h60
  text "V4.0" at 9200.8,127.26 h60
  text "2022/04/22" at 9685.8,122.26 h60
  text "Walt" at 8000.8,117.26 h60
  text "Standard" at 7300.8,112.26 h60
  text "Page   of" at 8650.8,-147.74 h60
  text "Approve" at 7315.8,-162.74 h60
  text "Linko Semiconductor" at 9585.8,-172.74 h60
